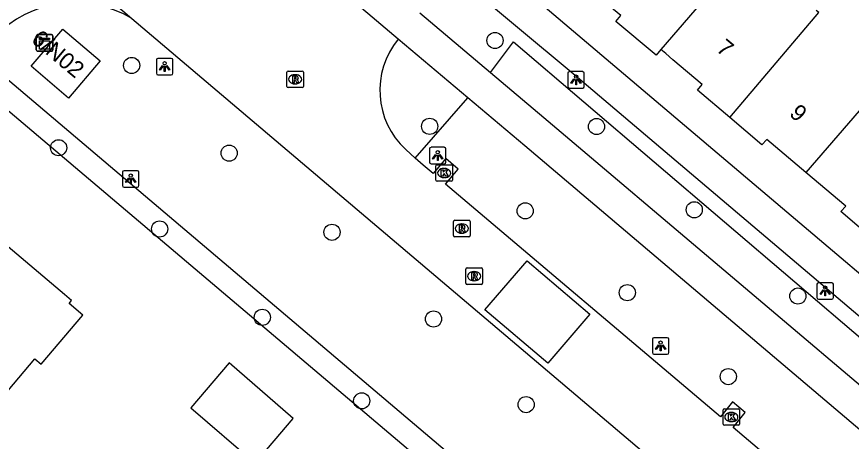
# Model space of a CAD drawing. Extents: x 156414 to 157775, y 382335 to 383765.
# Drawn here: x 156837.1 to 156887.7, y 382467.9 to 382493.6 of the extents above; entities that cross this region are included whole.
import ezdxf

# ---------------------------------------------------------------- set-up
doc = ezdxf.new("R2010")
doc.units = 0
for name, color, linetype in [('IMGEO_Boom', 7, 'Continuous'), ('IMGEO_Haag', 7, 'Continuous'), ('IMGEO_Kast', 7, 'Continuous'), ('IMGEO_Kolk', 7, 'Continuous'), ('IMGEO_Lichtpunt', 7, 'Continuous'), ('IMGEO_Pand', 7, 'Continuous'), ('IMGEO_Pand_nummerreeks', 7, 'Continuous'), ('IMGEO_Rijbaan_lokaal_open', 7, 'Continuous'), ('IMGEO_Rioolput', 7, 'Continuous'), ('IMGEO_Voetpad_open', 7, 'Continuous')]:
    doc.layers.add(name, color=color, linetype=linetype)

msp = doc.modelspace()

# ---------------------------------------------------------------- linework, layer by layer
at = {"layer": 'IMGEO_Boom'}
for centre in [(156866.109, 382492.136), (156844.096, 382490.626), (156862.152, 382486.935), (156872.259, 382486.924), (156839.673, 382485.638), (156850.005, 382485.314), (156867.938, 382481.814), (156878.179, 382481.881), (156845.791, 382480.717), (156856.233, 382480.517), (156874.123, 382476.86), (156884.455, 382476.654), (156852.01, 382475.363), (156862.384, 382475.264), (156880.241, 382471.772), (156858.034, 382470.304), (156867.993, 382470.076)]:
    msp.add_circle(centre, 0.489, dxfattribs=at)
at = {"layer": 'IMGEO_Haag'}
for points in [[(156865.838, 382490.195), (156867.222, 382492.051), (156892.793, 382470.251)], [(156861.282, 382485.009), (156864.461, 382488.664)]]:
    msp.add_lwpolyline(points, dxfattribs=at)
at = {"layer": 'IMGEO_Kast'}
for p, q in [((156838.319, 382491.566), (156838.319, 382492.407)), ((156838.319, 382492.407), (156838.319, 382491.566)), ((156838.394, 382492.491), (156839.235, 382492.491)), ((156839.235, 382492.491), (156838.394, 382492.491)), ((156839.319, 382492.416), (156839.319, 382491.575)), ((156839.319, 382491.575), (156839.319, 382492.416)), ((156839.244, 382491.491), (156838.403, 382491.491)), ((156838.403, 382491.491), (156839.244, 382491.491))]:
    msp.add_line(p, q, dxfattribs=at)
for points in [[(156838.514, 382492.281), (156839.114, 382492.281), (156839.114, 382492.196), (156838.514, 382492.196), (156838.514, 382492.281)], [(156838.514, 382492.106), (156839.114, 382492.106), (156839.114, 382491.617), (156838.514, 382491.617), (156838.514, 382492.106)]]:
    msp.add_lwpolyline(points, dxfattribs=at)
msp.add_circle((156838.598, 382491.955), 0.0377, dxfattribs=at)
for centre, start, end in [((156838.397, 382492.413), 92.4484, 184.2845), ((156838.397, 382492.413), 92.4484, 184.2845), ((156839.241, 382492.413), 2.4484, 94.2845), ((156839.241, 382492.413), 2.4484, 94.2845), ((156838.397, 382491.569), 182.4484, 274.2845), ((156838.397, 382491.569), 182.4484, 274.2845), ((156839.241, 382491.569), 272.4484, 4.2845), ((156839.241, 382491.569), 272.4484, 4.2845)]:
    msp.add_arc(centre, 0.0779, start, end, dxfattribs=at)
at = {"layer": 'IMGEO_Kolk'}
for p, q in [((156862.53, 382483.682), (156862.53, 382484.534)), ((156862.605, 382484.608), (156863.457, 382484.608)), ((156863.531, 382484.534), (156863.531, 382483.682)), ((156863.018, 382484.388), (156863.043, 382484.388)), ((156863.457, 382483.608), (156862.605, 382483.608)), ((156863.041, 382483.828), (156863.016, 382483.828)), ((156880.002, 382469.825), (156880.854, 382469.825)), ((156879.927, 382468.899), (156879.927, 382469.751)), ((156880.415, 382469.605), (156880.44, 382469.605)), ((156880.928, 382469.751), (156880.928, 382468.899)), ((156880.854, 382468.825), (156880.002, 382468.825)), ((156880.438, 382469.045), (156880.413, 382469.045))]:
    msp.add_line(p, q, dxfattribs=at)
for points in [[(156862.53, 382483.682), (156862.53, 382484.534)], [(156862.605, 382484.608), (156863.457, 382484.608)], [(156863.531, 382484.534), (156863.531, 382483.682)], [(156862.851, 382484.308), (156862.974, 382484.308), (156862.974, 382484.157), (156863.104, 382484.308), (156863.268, 382484.308), (156863.122, 382484.157), (156863.275, 382483.908), (156863.123, 382483.908), (156863.038, 382484.072), (156862.974, 382484.005), (156862.974, 382483.908), (156862.851, 382483.908), (156862.851, 382484.308)], [(156863.457, 382483.608), (156862.605, 382483.608)], [(156880.002, 382469.825), (156880.854, 382469.825)], [(156879.927, 382468.899), (156879.927, 382469.751)], [(156880.248, 382469.525), (156880.371, 382469.525), (156880.371, 382469.374), (156880.501, 382469.525), (156880.665, 382469.525), (156880.519, 382469.374), (156880.672, 382469.125), (156880.52, 382469.125), (156880.435, 382469.289), (156880.371, 382469.222), (156880.371, 382469.125), (156880.248, 382469.125), (156880.248, 382469.525)], [(156880.928, 382469.751), (156880.928, 382468.899)], [(156880.854, 382468.825), (156880.002, 382468.825)]]:
    msp.add_lwpolyline(points, dxfattribs=at)
for centre, start, end in [((156862.607, 382484.532), 91.552, 178.448), ((156862.607, 382484.532), 91.552, 178.448), ((156863.455, 382484.532), 1.552, 88.448), ((156863.455, 382484.532), 1.552, 88.448), ((156862.607, 382483.684), 181.552, 268.448), ((156862.607, 382483.684), 181.552, 268.448), ((156863.455, 382483.684), 271.552, 358.448), ((156863.455, 382483.684), 271.552, 358.448), ((156880.004, 382469.749), 91.552, 178.448), ((156880.004, 382469.749), 91.552, 178.448), ((156880.852, 382469.749), 1.552, 88.448), ((156880.852, 382469.749), 1.552, 88.448), ((156880.004, 382468.901), 181.552, 268.448), ((156880.004, 382468.901), 181.552, 268.448), ((156880.852, 382468.901), 271.552, 358.448), ((156880.852, 382468.901), 271.552, 358.448)]:
    msp.add_arc(centre, 0.0765, start, end, dxfattribs=at)
for centre, major_axis, ratio, start_param, end_param in [((156863.017, 382484.108), (-0.387, 0.002), 0.722429, 4.712389, 7.853982), ((156863.042, 382484.108), (-0.39, 0.002), 0.717154, 1.570796, 4.712389), ((156880.414, 382469.325), (-0.387, 0.002), 0.722429, 4.712389, 7.853982), ((156880.439, 382469.325), (-0.39, 0.002), 0.717154, 1.570796, 4.712389)]:
    msp.add_ellipse(centre, major_axis=major_axis, ratio=ratio, start_param=start_param, end_param=end_param, dxfattribs=at)
at = {"layer": 'IMGEO_Lichtpunt'}
for p, q in [((156846.5, 382491.055), (156845.692, 382491.055)), ((156846.5, 382491.055), (156845.692, 382491.055)), ((156845.598, 382490.96), (156845.598, 382490.153)), ((156845.598, 382490.96), (156845.598, 382490.153)), ((156846.594, 382490.153), (156846.594, 382490.96)), ((156846.594, 382490.153), (156846.594, 382490.96)), ((156845.692, 382490.059), (156846.5, 382490.059)), ((156845.692, 382490.059), (156846.5, 382490.059)), ((156870.52, 382490.153), (156870.52, 382489.346)), ((156870.52, 382490.153), (156870.52, 382489.346)), ((156871.422, 382490.248), (156870.614, 382490.248)), ((156871.422, 382490.248), (156870.614, 382490.248)), ((156871.516, 382489.346), (156871.516, 382490.153)), ((156871.516, 382489.346), (156871.516, 382490.153)), ((156870.614, 382489.252), (156871.422, 382489.252)), ((156870.614, 382489.252), (156871.422, 382489.252)), ((156862.14, 382485.569), (156862.14, 382484.762)), ((156862.14, 382485.569), (156862.14, 382484.762)), ((156863.042, 382485.664), (156862.234, 382485.664)), ((156863.042, 382485.664), (156862.234, 382485.664)), ((156863.136, 382484.762), (156863.136, 382485.569)), ((156863.136, 382484.762), (156863.136, 382485.569)), ((156862.234, 382484.668), (156863.042, 382484.668)), ((156862.234, 382484.668), (156863.042, 382484.668)), ((156843.544, 382484.152), (156843.544, 382483.345)), ((156843.544, 382484.152), (156843.544, 382483.345)), ((156844.446, 382484.247), (156843.638, 382484.247)), ((156844.446, 382484.247), (156843.638, 382484.247)), ((156844.54, 382483.345), (156844.54, 382484.152)), ((156844.54, 382483.345), (156844.54, 382484.152)), ((156843.638, 382483.251), (156844.446, 382483.251)), ((156843.638, 382483.251), (156844.446, 382483.251)), ((156885.611, 382477.368), (156885.611, 382476.561)), ((156885.611, 382477.368), (156885.611, 382476.561)), ((156886.513, 382477.463), (156885.705, 382477.463)), ((156886.513, 382477.463), (156885.705, 382477.463)), ((156886.607, 382476.561), (156886.607, 382477.368)), ((156886.607, 382476.561), (156886.607, 382477.368)), ((156885.705, 382476.467), (156886.513, 382476.467)), ((156885.705, 382476.467), (156886.513, 382476.467)), ((156875.642, 382474.034), (156875.642, 382473.227)), ((156875.642, 382474.034), (156875.642, 382473.227)), ((156876.544, 382474.129), (156875.736, 382474.129)), ((156876.544, 382474.129), (156875.736, 382474.129)), ((156876.638, 382473.227), (156876.638, 382474.034)), ((156876.638, 382473.227), (156876.638, 382474.034)), ((156875.736, 382473.133), (156876.544, 382473.133)), ((156875.736, 382473.133), (156876.544, 382473.133))]:
    msp.add_line(p, q, dxfattribs=at)
for points in [[(156845.972, 382490.624), (156846.011, 382490.596), (156845.823, 382490.334), (156845.785, 382490.361), (156845.972, 382490.624)], [(156846.074, 382490.576), (156846.121, 382490.576), (156846.121, 382490.254), (156846.074, 382490.254), (156846.074, 382490.576)], [(156846.184, 382490.596), (156846.222, 382490.623), (156846.409, 382490.361), (156846.37, 382490.333), (156846.184, 382490.596)], [(156870.894, 382489.817), (156870.933, 382489.789), (156870.745, 382489.527), (156870.707, 382489.554), (156870.894, 382489.817)], [(156870.996, 382489.769), (156871.043, 382489.769), (156871.043, 382489.447), (156870.996, 382489.447), (156870.996, 382489.769)], [(156871.106, 382489.789), (156871.144, 382489.816), (156871.331, 382489.554), (156871.292, 382489.526), (156871.106, 382489.789)], [(156862.514, 382485.233), (156862.553, 382485.205), (156862.365, 382484.943), (156862.327, 382484.97), (156862.514, 382485.233)], [(156862.616, 382485.185), (156862.663, 382485.185), (156862.663, 382484.863), (156862.616, 382484.863), (156862.616, 382485.185)], [(156862.726, 382485.205), (156862.764, 382485.232), (156862.951, 382484.97), (156862.912, 382484.942), (156862.726, 382485.205)], [(156843.918, 382483.816), (156843.957, 382483.788), (156843.769, 382483.526), (156843.731, 382483.553), (156843.918, 382483.816)], [(156844.02, 382483.768), (156844.067, 382483.768), (156844.067, 382483.446), (156844.02, 382483.446), (156844.02, 382483.768)], [(156844.13, 382483.788), (156844.168, 382483.815), (156844.355, 382483.553), (156844.316, 382483.525), (156844.13, 382483.788)], [(156885.985, 382477.032), (156886.024, 382477.004), (156885.836, 382476.742), (156885.798, 382476.769), (156885.985, 382477.032)], [(156886.087, 382476.984), (156886.134, 382476.984), (156886.134, 382476.662), (156886.087, 382476.662), (156886.087, 382476.984)], [(156886.197, 382477.004), (156886.235, 382477.031), (156886.422, 382476.769), (156886.383, 382476.741), (156886.197, 382477.004)], [(156876.016, 382473.698), (156876.055, 382473.67), (156875.867, 382473.408), (156875.829, 382473.435), (156876.016, 382473.698)], [(156876.118, 382473.65), (156876.165, 382473.65), (156876.165, 382473.328), (156876.118, 382473.328), (156876.118, 382473.65)], [(156876.228, 382473.67), (156876.266, 382473.697), (156876.453, 382473.435), (156876.414, 382473.407), (156876.228, 382473.67)]]:
    msp.add_lwpolyline(points, dxfattribs=at)
for centre in [(156846.097, 382490.758), (156871.019, 382489.951), (156862.639, 382485.367), (156844.043, 382483.95), (156886.11, 382477.166), (156876.141, 382473.832)]:
    msp.add_circle(centre, 0.0994, dxfattribs=at)
for centre, start, end in [((156845.692, 382490.96), 90, 180), ((156845.692, 382490.96), 90, 180), ((156846.5, 382490.96), 0, 90), ((156846.5, 382490.96), 0, 90), ((156845.692, 382490.153), 180, 270), ((156845.692, 382490.153), 180, 270), ((156846.5, 382490.153), 270, 0), ((156846.5, 382490.153), 270, 360), ((156870.614, 382490.153), 90, 180), ((156870.614, 382490.153), 90, 180), ((156871.422, 382490.153), 0, 90), ((156871.422, 382490.153), 0, 90), ((156870.614, 382489.346), 180, 270), ((156870.614, 382489.346), 180, 270), ((156871.422, 382489.346), 270, 0), ((156871.422, 382489.346), 270, 360), ((156862.234, 382485.569), 90, 180), ((156862.234, 382485.569), 90, 180), ((156863.042, 382485.569), 0, 90), ((156863.042, 382485.569), 0, 90), ((156862.234, 382484.762), 180, 270), ((156862.234, 382484.762), 180, 270), ((156863.042, 382484.762), 270, 0), ((156863.042, 382484.762), 270, 360), ((156843.638, 382484.152), 90, 180), ((156843.638, 382484.152), 90, 180), ((156844.446, 382484.152), 0, 90), ((156844.446, 382484.152), 0, 90), ((156843.638, 382483.345), 180, 270), ((156843.638, 382483.345), 180, 270), ((156844.446, 382483.345), 270, 0), ((156844.446, 382483.345), 270, 360), ((156885.705, 382477.368), 90, 180), ((156885.705, 382477.368), 90, 180), ((156886.513, 382477.368), 0, 90), ((156886.513, 382477.368), 0, 90), ((156885.705, 382476.561), 180, 270), ((156885.705, 382476.561), 180, 270), ((156886.513, 382476.561), 270, 0), ((156886.513, 382476.561), 270, 360), ((156875.736, 382474.034), 90, 180), ((156875.736, 382474.034), 90, 180), ((156876.544, 382474.034), 0, 90), ((156876.544, 382474.034), 0, 90), ((156875.736, 382473.227), 180, 270), ((156875.736, 382473.227), 180, 270), ((156876.544, 382473.227), 270, 0), ((156876.544, 382473.227), 270, 360)]:
    msp.add_arc(centre, 0.0946, start, end, dxfattribs=at)
at = {"layer": 'IMGEO_Pand'}
for points in [[(156876.155, 382491.595), (156875.863, 382491.256), (156873.432, 382493.297), (156873.726, 382493.645), (156871.721, 382495.337), (156877.405, 382502.024), (156882.1, 382497.998), (156881.543, 382497.369)], [(156881.543, 382497.369), (156881.301, 382497.575), (156876.155, 382491.595)], [(156880.337, 382487.466), (156885.718, 382493.833), (156885.573, 382493.956)], [(156840.271, 382488.647), (156838.008, 382490.575), (156839.927, 382492.83), (156842.197, 382490.901), (156840.271, 382488.647)], [(156880.337, 382487.466), (156878.371, 382489.133), (156878.661, 382489.47), (156876.89, 382490.972), (156876.452, 382491.343), (156876.155, 382491.595)], [(156891.713, 382491.658), (156890.113, 382490.118), (156884.943, 382484.14)], [(156884.943, 382484.14), (156882.58, 382486.144), (156882.272, 382485.824), (156880.337, 382487.466)], [(156889.019, 382480.107), (156887.065, 382481.767), (156887.352, 382482.097), (156884.943, 382484.14)], [(156834.658, 382468.629), (156838.242, 382472.852), (156838.619, 382472.532), (156841.136, 382475.498), (156840.305, 382476.203), (156840.46, 382476.386), (156840.033, 382476.745), (156835.544, 382480.522), (156833.182, 382477.737), (156830.134, 382480.326), (156826.257, 382475.755)], [(156850.01, 382472.602), (156847.682, 382469.885), (156851.58, 382466.52), (156853.883, 382469.24), (156850.01, 382472.602)]]:
    msp.add_lwpolyline(points, dxfattribs=at)
at = {"layer": 'IMGEO_Rijbaan_lokaal_open'}
for points in [[(156832.153, 382503.644), (156844.108, 382493.469)], [(156860.251, 382492.221), (156856.445, 382495.448)], [(156844.108, 382493.469), (156884.65, 382459.104)], [(156861.282, 382485.009), (156860.706, 382485.529)], [(156898.238, 382453.7), (156897.703, 382454.152), (156898.46, 382455.055), (156897.681, 382455.704), (156896.961, 382454.779), (156896.478, 382455.187), (156880.529, 382468.689), (156881.272, 382469.602), (156880.502, 382470.246), (156879.768, 382469.333), (156863.112, 382483.433), (156863.872, 382484.335), (156863.133, 382484.994), (156862.353, 382484.075), (156861.762, 382484.576), (156861.282, 382485.009)], [(156869.301, 382472.584), (156865.485, 382475.821), (156868.064, 382478.792), (156871.86, 382475.559), (156869.301, 382472.584)]]:
    msp.add_lwpolyline(points, dxfattribs=at)
for centre, radius, start, end in [((156840.652, 382487.711), 6.716, 59.0264, 136.4019), ((156863.999, 382489.114), 4.868, 140.3427, 227.4366)]:
    msp.add_arc(centre, radius, start, end, dxfattribs=at)
at = {"layer": 'IMGEO_Rioolput'}
for p, q in [((156853.499, 382489.359), (156853.499, 382490.211)), ((156853.574, 382490.285), (156854.426, 382490.285)), ((156853.987, 382490.065), (156854.012, 382490.065)), ((156854.5, 382490.211), (156854.5, 382489.359)), ((156854.01, 382489.505), (156853.985, 382489.505)), ((156854.426, 382489.285), (156853.574, 382489.285)), ((156863.596, 382480.316), (156863.596, 382481.168)), ((156863.671, 382481.242), (156864.523, 382481.242)), ((156864.084, 382481.022), (156864.109, 382481.022)), ((156864.597, 382481.168), (156864.597, 382480.316)), ((156864.107, 382480.462), (156864.082, 382480.462)), ((156864.523, 382480.242), (156863.671, 382480.242)), ((156864.422, 382478.36), (156865.274, 382478.36)), ((156864.347, 382477.434), (156864.347, 382478.286)), ((156864.835, 382478.14), (156864.86, 382478.14)), ((156865.348, 382478.286), (156865.348, 382477.434)), ((156865.274, 382477.36), (156864.422, 382477.36)), ((156864.858, 382477.58), (156864.833, 382477.58))]:
    msp.add_line(p, q, dxfattribs=at)
for points in [[(156853.499, 382489.359), (156853.499, 382490.211)], [(156853.574, 382490.285), (156854.426, 382490.285)], [(156854.088, 382489.983), (156853.836, 382489.985), (156853.836, 382489.585)], [(156854.5, 382490.211), (156854.5, 382489.359)], [(156853.836, 382489.585), (156853.96, 382489.585), (156853.96, 382489.747), (156853.971, 382489.747)], [(156854.014, 382489.904), (156853.96, 382489.904), (156853.96, 382489.823)], [(156853.96, 382489.823), (156854.012, 382489.823)], [(156854.018, 382489.718), (156854.089, 382489.585), (156854.229, 382489.585), (156854.164, 382489.711)], [(156854.426, 382489.285), (156853.574, 382489.285)], [(156863.596, 382480.316), (156863.596, 382481.168)], [(156863.671, 382481.242), (156864.523, 382481.242)], [(156864.185, 382480.94), (156863.933, 382480.942), (156863.933, 382480.542)], [(156864.597, 382481.168), (156864.597, 382480.316)], [(156863.933, 382480.542), (156864.057, 382480.542), (156864.057, 382480.704), (156864.068, 382480.704)], [(156864.111, 382480.861), (156864.057, 382480.861), (156864.057, 382480.78)], [(156864.057, 382480.78), (156864.109, 382480.78)], [(156864.115, 382480.675), (156864.186, 382480.542), (156864.326, 382480.542), (156864.261, 382480.668)], [(156864.523, 382480.242), (156863.671, 382480.242)], [(156864.422, 382478.36), (156865.274, 382478.36)], [(156864.347, 382477.434), (156864.347, 382478.286)], [(156864.936, 382478.058), (156864.684, 382478.06), (156864.684, 382477.66)], [(156864.862, 382477.979), (156864.808, 382477.979), (156864.808, 382477.898)], [(156864.808, 382477.898), (156864.86, 382477.898)], [(156865.348, 382478.286), (156865.348, 382477.434)], [(156865.274, 382477.36), (156864.422, 382477.36)], [(156864.684, 382477.66), (156864.808, 382477.66), (156864.808, 382477.822), (156864.819, 382477.822)], [(156864.866, 382477.793), (156864.937, 382477.66), (156865.077, 382477.66), (156865.012, 382477.786)]]:
    msp.add_lwpolyline(points, dxfattribs=at)
for centre, radius, start, end in [((156853.576, 382490.209), 0.0765, 91.552, 178.448), ((156853.576, 382490.209), 0.0765, 91.552, 178.448), ((156854.087, 382489.873), 0.109, 350.3612, 89.416), ((156854.424, 382490.209), 0.0765, 1.552, 88.448), ((156854.424, 382490.209), 0.0765, 1.552, 88.448), ((156853.97, 382489.694), 0.0533, 26.0293, 88.6989), ((156853.996, 382490.012), 0.19, 274.7715, 282.9687), ((156854.02, 382489.808), 0.0964, 77.0061, 93.1865), ((156854.034, 382489.865), 0.0378, 276.6634, 79.6772), ((156854.085, 382489.873), 0.112, 277.5842, 350.9817), ((156854.069, 382489.658), 0.108, 29.5134, 73.7905), ((156853.576, 382489.361), 0.0765, 181.552, 268.448), ((156853.576, 382489.361), 0.0765, 181.552, 268.448), ((156854.424, 382489.361), 0.0765, 271.552, 358.448), ((156854.424, 382489.361), 0.0765, 271.552, 358.448), ((156863.673, 382481.166), 0.0765, 91.552, 178.448), ((156863.673, 382481.166), 0.0765, 91.552, 178.448), ((156864.184, 382480.83), 0.109, 350.3612, 89.416), ((156864.521, 382481.166), 0.0765, 1.552, 88.448), ((156864.521, 382481.166), 0.0765, 1.552, 88.448), ((156864.067, 382480.651), 0.0533, 26.0293, 88.6989), ((156864.093, 382480.969), 0.19, 274.7715, 282.9687), ((156864.117, 382480.765), 0.0964, 77.0061, 93.1865), ((156864.131, 382480.822), 0.0378, 276.6634, 79.6772), ((156864.182, 382480.83), 0.112, 277.5842, 350.9817), ((156864.166, 382480.615), 0.108, 29.5134, 73.7905), ((156863.673, 382480.318), 0.0765, 181.552, 268.448), ((156863.673, 382480.318), 0.0765, 181.552, 268.448), ((156864.521, 382480.318), 0.0765, 271.552, 358.448), ((156864.521, 382480.318), 0.0765, 271.552, 358.448), ((156864.424, 382478.284), 0.0765, 91.552, 178.448), ((156864.424, 382478.284), 0.0765, 91.552, 178.448), ((156865.272, 382478.284), 0.0765, 1.552, 88.448), ((156865.272, 382478.284), 0.0765, 1.552, 88.448), ((156864.844, 382478.087), 0.19, 274.7715, 282.9687), ((156864.868, 382477.883), 0.0964, 77.0061, 93.1865), ((156864.882, 382477.94), 0.0378, 276.6634, 79.6772), ((156864.935, 382477.948), 0.109, 350.3612, 89.416), ((156864.933, 382477.948), 0.112, 277.5842, 350.9817), ((156864.424, 382477.436), 0.0765, 181.552, 268.448), ((156864.424, 382477.436), 0.0765, 181.552, 268.448), ((156864.818, 382477.769), 0.0533, 26.0293, 88.6989), ((156864.917, 382477.733), 0.108, 29.5134, 73.7905), ((156865.272, 382477.436), 0.0765, 271.552, 358.448), ((156865.272, 382477.436), 0.0765, 271.552, 358.448)]:
    msp.add_arc(centre, radius, start, end, dxfattribs=at)
for centre, major_axis, ratio, start_param, end_param in [((156853.986, 382489.785), (-0.387, 0.002), 0.722429, 4.712389, 7.853982), ((156854.011, 382489.785), (-0.39, 0.002), 0.717154, 1.570796, 4.712389), ((156864.083, 382480.742), (-0.387, 0.002), 0.722429, 4.712389, 7.853982), ((156864.108, 382480.742), (-0.39, 0.002), 0.717154, 1.570796, 4.712389), ((156864.834, 382477.86), (-0.387, 0.002), 0.722429, 4.712389, 7.853982), ((156864.859, 382477.86), (-0.39, 0.002), 0.717154, 1.570796, 4.712389)]:
    msp.add_ellipse(centre, major_axis=major_axis, ratio=ratio, start_param=start_param, end_param=end_param, dxfattribs=at)
at = {"layer": 'IMGEO_Voetpad_open'}
for points in [[(156893.399, 382470.983), (156870.843, 382490.126), (156863.984, 382495.86)], [(156869.142, 382494.152), (156906.194, 382462.781)], [(156861.565, 382493.813), (156865.838, 382490.195)], [(156864.461, 382488.664), (156860.251, 382492.221)], [(156878.866, 382453.93), (156834.843, 382491.235)], [(156865.838, 382490.195), (156869.063, 382487.465), (156891.396, 382468.566), (156892.793, 382470.251)], [(156835.001, 382489.257), (156877.342, 382453.394)], [(156901.478, 382457.302), (156867.914, 382485.747), (156864.461, 382488.664)]]:
    msp.add_lwpolyline(points, dxfattribs=at)

# ---------------------------------------------------------------- texts
at = {"layer": 'IMGEO_Pand_nummerreeks'}
for s, rotation, p in [('6/N02', 320.0496, (156837.956, 382492.096)), ('7', 320.1451, (156879.457, 382491.539)), ('9', 317.0776, (156883.884, 382487.641))]:
    msp.add_text(s, height=1, rotation=rotation, dxfattribs=at).set_placement(p)

doc.saveas('drawing.dxf')
